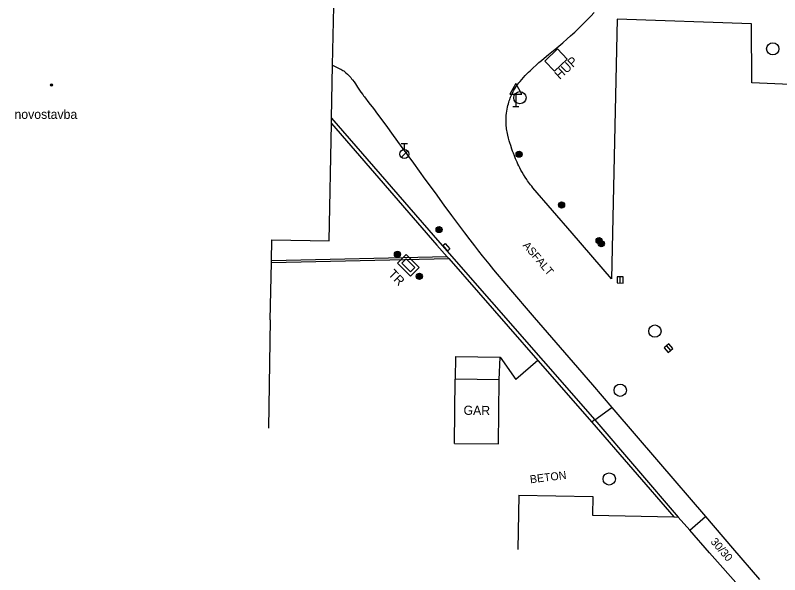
# Model space of a CAD drawing. Extents: x -538441 to -536770, y -1181008 to -1179809.
# Drawn here: x -537458.4 to -537395.9, y -1180861.3 to -1180815.6 of the extents above; entities that cross this region are included whole.
import ezdxf

# ---------------------------------------------------------------- set-up
doc = ezdxf.new("R2010")
doc.units = 0
for name, color, linetype in [('Vrstva 10', 7, 'Continuous'), ('Vrstva 11', 7, 'Continuous'), ('Vrstva 24', 7, 'Continuous'), ('Vrstva 25', 7, 'Continuous'), ('Vrstva 27', 7, 'Continuous'), ('Vrstva 28', 7, 'Continuous'), ('Vrstva 34', 7, 'Continuous'), ('Vrstva 39', 7, 'Continuous'), ('Vrstva 40', 7, 'Continuous'), ('Vrstva 41', 7, 'Continuous'), ('Vrstva 5', 7, 'Continuous'), ('Vrstva 7', 7, 'Continuous')]:
    doc.layers.add(name, color=color, linetype=linetype)

msp = doc.modelspace()

# ---------------------------------------------------------------- linework, layer by layer
at = {"layer": 'Vrstva 10'}
for p, q in [((-537409.62, -1180847.62), (-537405.79, -1180852.08)), ((-537405.79, -1180852.08), (-537401.96, -1180856.54))]:
    msp.add_line(p, q, dxfattribs=at)
for points in [[(-537416.682, -1180820.5), (-537416.546, -1180820.359), (-537416.414, -1180820.225), (-537416.284, -1180820.098), (-537416.032, -1180819.856), (-537415.792, -1180819.636), (-537415.567, -1180819.433), (-537415.354, -1180819.248), (-537415.154, -1180819.076), (-537414.777, -1180818.759), (-537414.118, -1180818.214), (-537413.626, -1180817.805), (-537413.262, -1180817.494), (-537412.991, -1180817.257), (-537412.79, -1180817.075), (-537412.641, -1180816.937), (-537412.419, -1180816.726), (-537412.2, -1180816.51), (-537411.705, -1180816.007), (-537411.337, -1180815.626), (-537411.064, -1180815.337)], [(-537432.43, -1180819.633), (-537431.837, -1180819.929), (-537431.753, -1180819.973), (-537431.673, -1180820.019), (-537431.599, -1180820.067), (-537431.528, -1180820.115), (-537431.462, -1180820.165), (-537431.399, -1180820.215), (-537431.339, -1180820.265), (-537431.227, -1180820.367), (-537431.127, -1180820.467), (-537431.035, -1180820.566), (-537430.952, -1180820.662), (-537430.876, -1180820.754), (-537430.807, -1180820.843), (-537430.68, -1180821.013), (-537430.572, -1180821.166), (-537430.388, -1180821.438), (-537430.113, -1180821.847), (-537429.974, -1180822.047), (-537429.902, -1180822.144), (-537429.83, -1180822.24), (-537429.458, -1180822.725), (-537429.1, -1180823.196), (-537428.754, -1180823.654), (-537428.091, -1180824.545), (-537427.473, -1180825.383), (-537426.897, -1180826.171)], [(-537416.156, -1180829.546), (-537416.247, -1180829.433), (-537416.333, -1180829.322), (-537416.415, -1180829.212), (-537416.492, -1180829.104), (-537416.565, -1180828.998), (-537416.703, -1180828.789), (-537416.826, -1180828.589), (-537416.938, -1180828.398), (-537417.038, -1180828.216), (-537417.129, -1180828.044), (-537417.211, -1180827.88), (-537417.285, -1180827.726), (-537417.352, -1180827.58), (-537417.473, -1180827.304), (-537417.573, -1180827.061), (-537417.655, -1180826.848), (-537417.724, -1180826.66), (-537417.782, -1180826.497), (-537417.877, -1180826.21), (-537417.943, -1180825.996), (-537417.991, -1180825.835), (-537418.058, -1180825.597), (-537418.12, -1180825.36), (-537418.151, -1180825.229), (-537418.178, -1180825.099), (-537418.2, -1180824.972), (-537418.218, -1180824.847), (-537418.232, -1180824.725), (-537418.243, -1180824.606), (-537418.251, -1180824.489), (-537418.256, -1180824.376), (-537418.259, -1180824.265), (-537418.259, -1180824.157), (-537418.257, -1180824.052), (-537418.253, -1180823.95), (-537418.239, -1180823.751), (-537418.22, -1180823.565), (-537418.195, -1180823.39), (-537418.167, -1180823.226), (-537418.136, -1180823.073), (-537418.103, -1180822.93), (-537418.068, -1180822.797), (-537418.032, -1180822.673), (-537417.995, -1180822.557), (-537417.958, -1180822.449), (-537417.921, -1180822.349), (-537417.885, -1180822.255), (-537417.812, -1180822.082), (-537417.742, -1180821.933), (-537417.677, -1180821.804), (-537417.617, -1180821.693), (-537417.561, -1180821.598), (-537417.511, -1180821.515), (-537417.419, -1180821.373), (-537417.347, -1180821.269), (-537417.29, -1180821.192), (-537417.202, -1180821.08), (-537417.11, -1180820.97), (-537416.964, -1180820.805), (-537416.822, -1180820.649), (-537416.682, -1180820.5)], [(-537426.897, -1180826.171), (-537425.823, -1180827.653), (-537424.885, -1180828.951), (-537424.063, -1180830.085), (-537423.341, -1180831.074), (-537422.705, -1180831.937), (-537422.145, -1180832.689), (-537421.651, -1180833.343), (-537421.216, -1180833.914)], [(-537409.64, -1180837.11), (-537412.85, -1180833.385), (-537416.06, -1180829.66), (-537416.156, -1180829.546)], [(-537421.216, -1180833.914), (-537420.833, -1180834.411), (-537420.495, -1180834.844), (-537420.198, -1180835.222)], [(-537420.198, -1180835.222), (-537419.673, -1180835.879), (-537419.276, -1180836.369), (-537418.975, -1180836.734), (-537418.52, -1180837.279), (-537418.06, -1180837.82), (-537415.951, -1180840.271)], [(-537415.951, -1180840.271), (-537412.784, -1180843.944), (-537411.201, -1180845.781), (-537409.62, -1180847.62)], [(-537401.96, -1180856.54), (-537399.745, -1180859.114), (-537397.53, -1180861.69)]]:
    msp.add_lwpolyline(points, dxfattribs=at)
at = {"layer": 'Vrstva 11'}
for p, q in [((-537409.17, -1180815.87), (-537409.64, -1180837.11)), ((-537398.2, -1180816.26), (-537409.17, -1180815.87)), ((-537398.18, -1180821.09), (-537398.2, -1180816.26)), ((-537377.522, -1180822.026), (-537398.18, -1180821.09)), ((-537418.74, -1180843.51), (-537417.45, -1180845.33)), ((-537415.669, -1180843.772), (-537417.45, -1180845.33)), ((-537411.01, -1180848.64), (-537409.62, -1180847.62)), ((-537403.234, -1180857.664), (-537401.96, -1180856.54))]:
    msp.add_line(p, q, dxfattribs=at)
at = {"layer": 'Vrstva 24'}
for p, q in [((-537414.05, -1180818.32), (-537415.096, -1180819.302)), ((-537413.264, -1180819.158), (-537414.05, -1180818.32)), ((-537415.096, -1180819.302), (-537414.31, -1180820.14)), ((-537414.31, -1180820.14), (-537413.264, -1180819.158)), ((-537423.425, -1180834.39), (-537423.24, -1180834.23)), ((-537423.425, -1180834.39), (-537423.036, -1180834.84)), ((-537423.24, -1180834.23), (-537422.84, -1180834.67)), ((-537426.409, -1180835.116), (-537427.117, -1180835.82)), ((-537425.353, -1180836.18), (-537426.409, -1180835.116)), ((-537423.036, -1180834.84), (-537422.84, -1180834.67)), ((-537426.409, -1180835.468), (-537426.765, -1180835.822)), ((-537425.705, -1180836.178), (-537426.409, -1180835.468)), ((-537427.117, -1180835.82), (-537426.061, -1180836.884)), ((-537426.765, -1180835.822), (-537426.061, -1180836.532)), ((-537426.061, -1180836.532), (-537425.705, -1180836.178)), ((-537426.061, -1180836.884), (-537425.353, -1180836.18))]:
    msp.add_line(p, q, dxfattribs=at)
at = {"layer": 'Vrstva 25'}
for centre, radius in [((-537417.19, -1180826.92), 0.25), ((-537417.19, -1180826.92), 0.2), ((-537417.19, -1180826.92), 0.15), ((-537417.19, -1180826.92), 0.1), ((-537417.19, -1180826.92), 0.05), ((-537413.72, -1180831.07), 0.25), ((-537413.72, -1180831.07), 0.2), ((-537413.72, -1180831.07), 0.15), ((-537413.72, -1180831.07), 0.1), ((-537413.72, -1180831.07), 0.05), ((-537423.73, -1180833.08), 0.25), ((-537423.73, -1180833.08), 0.2), ((-537423.73, -1180833.08), 0.15), ((-537423.73, -1180833.08), 0.1), ((-537423.73, -1180833.08), 0.05), ((-537410.65, -1180833.99), 0.25), ((-537410.65, -1180833.99), 0.2), ((-537410.65, -1180833.99), 0.15), ((-537410.65, -1180833.99), 0.1), ((-537410.65, -1180833.99), 0.05), ((-537410.47, -1180834.24), 0.25), ((-537410.47, -1180834.24), 0.2), ((-537410.47, -1180834.24), 0.15), ((-537410.47, -1180834.24), 0.1), ((-537410.47, -1180834.24), 0.05), ((-537427.13, -1180835.1), 0.25), ((-537427.13, -1180835.1), 0.2), ((-537427.13, -1180835.1), 0.15), ((-537427.13, -1180835.1), 0.1), ((-537427.13, -1180835.1), 0.05), ((-537425.34, -1180836.9), 0.25), ((-537425.34, -1180836.9), 0.2), ((-537425.34, -1180836.9), 0.15), ((-537425.34, -1180836.9), 0.1), ((-537425.34, -1180836.9), 0.05)]:
    msp.add_circle(centre, radius, dxfattribs=at)
at = {"layer": 'Vrstva 27'}
for p, q in [((-537408.936, -1180837.45), (-537408.924, -1180836.95)), ((-537405.143, -1180842.591), (-537404.817, -1180842.969))]:
    msp.add_line(p, q, dxfattribs=at)
for points in [[(-537408.686, -1180837.455), (-537408.675, -1180836.956), (-537409.174, -1180836.945), (-537409.185, -1180837.444)], [(-537405.333, -1180842.754), (-537405.006, -1180843.133), (-537404.627, -1180842.806), (-537404.954, -1180842.427)]]:
    msp.add_lwpolyline(points, close=True, dxfattribs=at)
for centre in [(-537396.46, -1180818.31), (-537417.12, -1180822.3), (-537406.09, -1180841.38), (-537408.92, -1180846.22), (-537409.82, -1180853.47)]:
    msp.add_circle(centre, 0.5, dxfattribs=at)
at = {"layer": 'Vrstva 28'}
for p, q in [((-537426.817, -1180826.033), (-537426.317, -1180826.033)), ((-537426.567, -1180826.533), (-537426.567, -1180826.033)), ((-537426.825, -1180827.18), (-537426.295, -1180826.65))]:
    msp.add_line(p, q, dxfattribs=at)
msp.add_circle((-537426.567, -1180826.908), 0.375, dxfattribs=at)
at = {"layer": 'Vrstva 34'}
for p, q in [((-537417.459, -1180822.007), (-537417.459, -1180823.025)), ((-537417.709, -1180823.025), (-537417.209, -1180823.025))]:
    msp.add_line(p, q, dxfattribs=at)
msp.add_lwpolyline([(-537417.959, -1180822.007), (-537416.959, -1180822.007), (-537417.459, -1180821.141)], close=True, dxfattribs=at)
at = {"layer": 'Vrstva 39'}
for radius in [0.09, 0.0398]:
    msp.add_circle((-537455.41, -1180821.266), radius, dxfattribs=at)
at = {"layer": 'Vrstva 5'}
for p, q in [((-537437.406, -1180833.926), (-537432.707, -1180834.014)), ((-537437.532, -1180840.473), (-537437.658, -1180849.305)), ((-537422.398, -1180843.468), (-537422.419, -1180845.318)), ((-537422.398, -1180843.468), (-537418.74, -1180843.51)), ((-537418.82, -1180845.36), (-537418.74, -1180843.51)), ((-537422.479, -1180850.568), (-537422.419, -1180845.318)), ((-537418.82, -1180845.36), (-537422.419, -1180845.318)), ((-537418.88, -1180850.61), (-537418.82, -1180845.36)), ((-537422.479, -1180850.568), (-537418.88, -1180850.61)), ((-537417.22, -1180854.8), (-537417.301, -1180859.242)), ((-537417.22, -1180854.8), (-537411.17, -1180854.91)), ((-537411.17, -1180854.91), (-537411.198, -1180856.422)), ((-537399.04, -1180862.42), (-537401.615, -1180859.5))]:
    msp.add_line(p, q, dxfattribs=at)
for points in [[(-537432.43, -1180819.633), (-537432.314, -1180813.615)], [(-537432.513, -1180823.964), (-537432.43, -1180819.633)], [(-537432.707, -1180834.014), (-537432.522, -1180824.412)], [(-537432.522, -1180824.412), (-537432.513, -1180823.964)], [(-537437.439, -1180835.624), (-537437.406, -1180833.926)], [(-537437.532, -1180840.473), (-537437.435, -1180835.773)], [(-537437.435, -1180835.773), (-537437.439, -1180835.624)], [(-537411.198, -1180856.422), (-537404.546, -1180856.572), (-537404.19, -1180856.58)], [(-537401.615, -1180859.5), (-537403.234, -1180857.664), (-537404.19, -1180856.58)]]:
    msp.add_lwpolyline(points, dxfattribs=at)
at = {"layer": 'Vrstva 7'}
for p, q in [((-537432.522, -1180824.412), (-537423.906, -1180834.357)), ((-537432.513, -1180823.964), (-537423.68, -1180834.16)), ((-537423.072, -1180835.31), (-537437.439, -1180835.624)), ((-537437.435, -1180835.773), (-537422.944, -1180835.456)), ((-537411.236, -1180848.838), (-537404.546, -1180856.572)), ((-537411.01, -1180848.64), (-537404.19, -1180856.58))]:
    msp.add_line(p, q, dxfattribs=at)
for points in [[(-537423.906, -1180834.357), (-537423.072, -1180835.31), (-537422.944, -1180835.456)], [(-537423.68, -1180834.16), (-537411.01, -1180848.64)], [(-537422.944, -1180835.456), (-537415.669, -1180843.772)], [(-537415.669, -1180843.772), (-537411.236, -1180848.838)], [(-537411.01, -1180848.64), (-537411.041, -1180848.663), (-537411.236, -1180848.838)]]:
    msp.add_lwpolyline(points, dxfattribs=at)

# ---------------------------------------------------------------- texts
at = {"layer": 'Vrstva 40'}
for s, rotation, p in [('ASFALT', 310.43835, (-537416.935, -1180834.402)), ('BETON', 7.22925, (-537416.264, -1180853.829)), ('30/30', 310.72706, (-537401.583, -1180858.624))]:
    msp.add_text(s, height=0.65, rotation=rotation, dxfattribs=at).set_placement(p)
at = {"layer": 'Vrstva 41'}
for s, rotation, p in [('HUP', 43.19245, (-537413.861, -1180820.861)), ('TR', 314.83784, (-537427.94, -1180836.784)), ('GAR', 359.33139, (-537421.734, -1180848.222))]:
    msp.add_text(s, height=0.75, rotation=rotation, dxfattribs=at).set_placement(p)
msp.add_text('novostavba', height=0.75, dxfattribs=at).set_placement((-537458.433, -1180824.032))

doc.saveas('drawing.dxf')
